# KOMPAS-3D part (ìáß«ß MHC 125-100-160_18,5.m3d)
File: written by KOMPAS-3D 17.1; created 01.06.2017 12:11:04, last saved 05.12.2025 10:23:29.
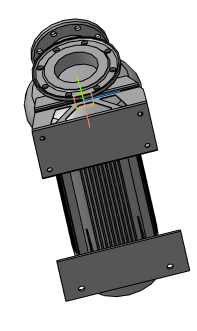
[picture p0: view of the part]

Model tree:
1. Операция без истории:2

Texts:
  ООО АДЛ ГРУПП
